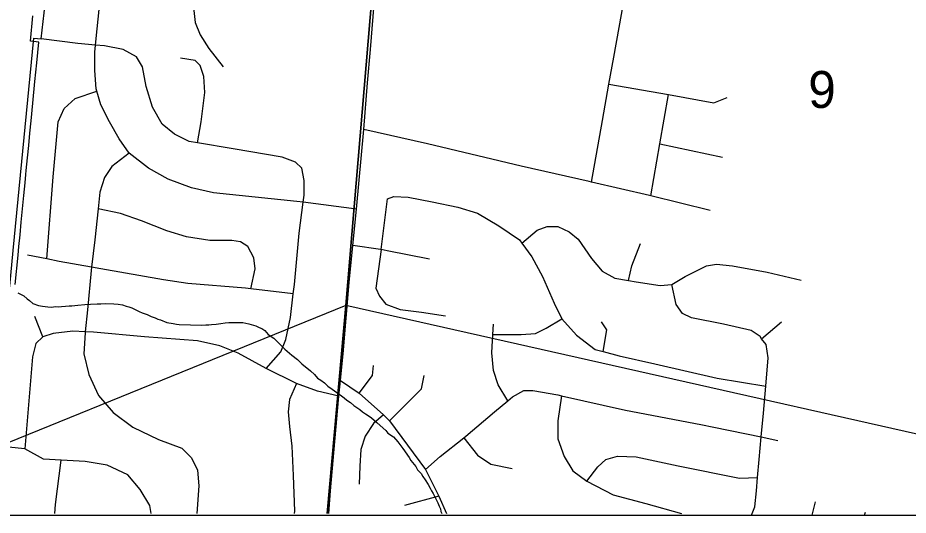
# Model space of a CAD drawing. Extents: x 0 to 34, y 0 to 22.
# Drawn here: x 7.262 to 8.273, y 14 to 14.564 of the extents above; entities that cross this region are included whole.
import ezdxf

# ---------------------------------------------------------------- set-up
doc = ezdxf.new("R2010")
doc.units = 0
for name, color, linetype in [('GM_X_City_Street', 7, 'Continuous'), ('GM_X_Interchange_Ramps', 7, 'Continuous'), ('GM_X_Minor_River', 7, 'Continuous'), ('GM_X_Section', 7, 'Continuous'), ('GM_X_Section_Text', 7, 'Continuous'), ('GM_X_State_Route', 7, 'Continuous'), ('GM_X_State_Shield', 7, 'Continuous'), ('GM_X_Township_Road', 7, 'Continuous'), ('SH_Data', 7, 'Continuous')]:
    doc.layers.add(name, color=color, linetype=linetype)

msp = doc.modelspace()

# ---------------------------------------------------------------- linework, layer by layer
at = {"layer": 'GM_X_City_Street'}
msp.add_lwpolyline([(7.2308, 14.2339), (7.2374, 14.2368), (7.2449, 14.2433), (7.2492, 14.2485), (7.2518, 14.2535), (7.2533, 14.2597), (7.2572, 14.3004), (7.2806, 14.5413), (7.289, 14.5407)], dxfattribs=at)
at = {"layer": 'GM_X_Interchange_Ramps'}
msp.add_lwpolyline([(7.2596, 14.2618), (7.2628, 14.2952), (7.2637, 14.3047), (7.265, 14.3183), (7.2664, 14.3324), (7.2679, 14.3475), (7.2694, 14.3629), (7.2707, 14.3771), (7.2717, 14.3866), (7.2721, 14.3912), (7.2735, 14.4053), (7.2749, 14.4194), (7.2762, 14.4335), (7.2776, 14.4476), (7.2795, 14.4676), (7.2819, 14.4922), (7.284, 14.5132), (7.2863, 14.5368), (7.2768, 14.5377), (7.2796, 14.5666)], dxfattribs=at)
at = {"layer": 'GM_X_Minor_River'}
for points in [[(7.2624, 14.2522), (7.2654, 14.2509), (7.2692, 14.249), (7.2729, 14.2454), (7.2759, 14.2435), (7.2796, 14.2403), (7.286, 14.2379), (7.2906, 14.237), (7.2967, 14.2365), (7.3012, 14.236), (7.305, 14.2367), (7.3084, 14.2366), (7.3119, 14.2369), (7.3164, 14.2371), (7.3206, 14.2374), (7.3237, 14.2377), (7.3305, 14.2383), (7.3385, 14.2389), (7.345, 14.2395), (7.3526, 14.2397), (7.3568, 14.2399), (7.3625, 14.2402), (7.3713, 14.24), (7.3762, 14.2395), (7.3811, 14.2386), (7.3853, 14.2373), (7.3883, 14.2365), (7.3917, 14.2353), (7.4, 14.2313), (7.4037, 14.2297), (7.4094, 14.2276), (7.4139, 14.2256), (7.4184, 14.224), (7.4214, 14.2224), (7.4244, 14.2215), (7.4316, 14.2187), (7.4388, 14.2174)], [(7.4388, 14.2174), (7.4426, 14.2169), (7.4456, 14.2165), (7.4711, 14.2158), (7.4757, 14.2161), (7.4791, 14.216), (7.4821, 14.2163), (7.4875, 14.2166), (7.4928, 14.2176), (7.4978, 14.2182), (7.502, 14.2185), (7.5065, 14.2188), (7.5111, 14.2187), (7.5179, 14.2185), (7.5213, 14.218), (7.5247, 14.2172), (7.5323, 14.2147), (7.5364, 14.2131), (7.5394, 14.2119), (7.5428, 14.2095), (7.5465, 14.2049), (7.5529, 14.2009), (7.561, 14.1931), (7.5655, 14.1884), (7.5733, 14.1814), (7.5796, 14.1767), (7.5848, 14.1716), (7.5945, 14.1637), (7.599, 14.1595), (7.6023, 14.1556), (7.6061, 14.1532), (7.6102, 14.1501), (7.6143, 14.1465), (7.6191, 14.143), (7.6244, 14.1391), (7.6296, 14.1355), (7.6326, 14.1332), (7.6359, 14.1304), (7.6397, 14.1277), (7.6438, 14.1245), (7.6505, 14.1198), (7.6535, 14.1174), (7.6568, 14.1151), (7.6598, 14.1131), (7.6636, 14.1103), (7.6699, 14.1052), (7.6736, 14.1017), (7.68, 14.0962), (7.6822, 14.0931), (7.6885, 14.0888), (7.6937, 14.0834), (7.6992, 14.0756), (7.7066, 14.0656), (7.7084, 14.0621), (7.7139, 14.0551), (7.7158, 14.0516), (7.7202, 14.0473), (7.722, 14.0439), (7.7246, 14.04), (7.7279, 14.035), (7.7304, 14.0307), (7.7319, 14.0277), (7.7337, 14.0246), (7.737, 14.0177), (7.7388, 14.0142), (7.7406, 14.0103), (7.742, 14.0073), (7.7423, 14.0042), (7.7435, 14.0019)]]:
    msp.add_lwpolyline(points, dxfattribs=at)
at = {"layer": 'GM_X_Section'}
msp.add_lwpolyline([(6.6081, 14.0019), (6.679, 14.8357), (7.7155, 15.1965), (7.6347, 14.2379), (7.0538, 14.0019)], dxfattribs=at)
msp.add_lwpolyline([(7.7155, 15.1965), (8.7359, 15.0399), (8.6553, 14.0079), (7.6347, 14.2379)], close=True, dxfattribs=at)
at = {"layer": 'GM_X_State_Route'}
for points in [[(7.6593, 14.4904), (7.6625, 14.5284), (7.6699, 14.6176), (7.6768, 14.6878), (7.6771, 14.6919)], [(7.6154, 14.0019), (7.6173, 14.0275), (7.6244, 14.1094), (7.6268, 14.135), (7.6285, 14.1527), (7.6314, 14.183), (7.6385, 14.2639), (7.6427, 14.3062), (7.6467, 14.3474), (7.6549, 14.4377), (7.6593, 14.4904)]]:
    msp.add_lwpolyline(points, dxfattribs=at)
at = {"layer": 'GM_X_State_Shield'}
for points in [[(7.6133, 14.0019), (7.6347, 14.2379), (7.0538, 14.0019)], [(8.6547, 14.0019), (8.6553, 14.0079), (7.6347, 14.2379), (7.6133, 14.0019)]]:
    msp.add_lwpolyline(points, dxfattribs=at)
at = {"layer": 'GM_X_Township_Road'}
for p, q in [((7.9909, 14.4215), (8.062, 14.4063)), ((7.7294, 14.2905), (7.6815, 14.3001)), ((7.2907, 14.2025), (7.2818, 14.2255)), ((8.1063, 14.2003), (8.1287, 14.2193)), ((7.74, 14.0215), (7.7011, 14.011)), ((8.1637, 14), (8.1673, 14.0151)), ((8.2229, 14), (8.2241, 14.0035))]:
    msp.add_line(p, q, dxfattribs=at)
for points in [[(7.289, 14.5407), (7.3026, 14.6589), (7.306, 14.743)], [(7.4307, 14.739), (7.43, 14.7358), (7.4276, 14.7145), (7.4248, 14.6922), (7.4276, 14.6839), (7.4373, 14.6797), (7.4554, 14.6714), (7.4609, 14.6631), (7.4651, 14.6506), (7.4651, 14.6325), (7.4623, 14.595), (7.4623, 14.5728), (7.4637, 14.5589), (7.4693, 14.545), (7.479, 14.5297), (7.4956, 14.5089)], [(7.9134, 14.378), (7.9256, 14.4478), (7.9331, 14.4891), (7.9387, 14.5196), (7.9508, 14.5873), (7.963, 14.6572)], [(7.6467, 14.3474), (7.5863, 14.3552), (7.579, 14.3561), (7.4845, 14.3658), (7.4595, 14.3714), (7.4331, 14.3811), (7.4109, 14.3936), (7.3887, 14.4109), (7.3776, 14.4269), (7.3665, 14.4464), (7.3568, 14.4658), (7.352, 14.4812), (7.3512, 14.4839), (7.3498, 14.5047), (7.3498, 14.5255), (7.3506, 14.5334), (7.3526, 14.5519), (7.3549, 14.5737), (7.3552, 14.5757)], [(7.5444, 14.1665), (7.5609, 14.1853), (7.5665, 14.1992), (7.572, 14.2242), (7.575, 14.2511), (7.5762, 14.2617), (7.5817, 14.32), (7.5863, 14.3552), (7.5873, 14.3631), (7.5873, 14.3797), (7.5845, 14.3936), (7.5776, 14.4006), (7.5623, 14.4061), (7.5068, 14.4158), (7.4662, 14.4226), (7.4568, 14.4241), (7.4401, 14.4325), (7.4262, 14.4436), (7.4151, 14.463), (7.4081, 14.4866), (7.404, 14.5089), (7.397, 14.52), (7.3818, 14.5283), (7.3609, 14.5325), (7.3506, 14.5334), (7.3304, 14.5353), (7.289, 14.5407)], [(7.4662, 14.4226), (7.4706, 14.4464), (7.4748, 14.4797), (7.4734, 14.4978), (7.4693, 14.5103), (7.4637, 14.5158), (7.447, 14.5186)], [(7.9331, 14.4891), (8.0006, 14.4772), (8.0519, 14.468), (8.0671, 14.4741)], [(7.2955, 14.2907), (7.3026, 14.3839), (7.3081, 14.4464), (7.3151, 14.4616), (7.3276, 14.4727), (7.352, 14.4812)], [(7.9806, 14.3625), (7.9909, 14.4215), (8.0006, 14.4772)], [(7.9105, 14.3787), (7.8336, 14.3962), (7.7274, 14.4215), (7.6549, 14.4377)], [(7.3887, 14.4109), (7.3693, 14.3956), (7.3609, 14.3831), (7.3554, 14.3665), (7.3535, 14.3478), (7.3498, 14.3123), (7.3461, 14.2816), (7.3456, 14.2776), (7.3415, 14.2332), (7.3388, 14.208), (7.3387, 14.2068), (7.3373, 14.1832), (7.3429, 14.1595), (7.354, 14.1359), (7.3706, 14.1165), (7.3929, 14.0998), (7.422, 14.0859), (7.4484, 14.0762), (7.4595, 14.0651), (7.4665, 14.0512), (7.4679, 14.0332), (7.4657, 14.0019)], [(8.0479, 14.3457), (7.9806, 14.3625), (7.9791, 14.3629), (7.9134, 14.378), (7.9105, 14.3787)], [(7.6745, 14.3015), (7.6819, 14.3588), (7.689, 14.3618), (7.7052, 14.3608), (7.7325, 14.3557), (7.7618, 14.3497), (7.784, 14.3426), (7.8083, 14.3285), (7.8315, 14.3123), (7.8343, 14.3085), (7.8457, 14.2931), (7.8578, 14.2708), (7.871, 14.2405), (7.8798, 14.2228), (7.8962, 14.2041), (7.9175, 14.1879), (7.9264, 14.1856), (7.9448, 14.1809), (7.9852, 14.1718), (8.056, 14.1556), (8.111, 14.1465)], [(7.5268, 14.2568), (7.5317, 14.2797), (7.5304, 14.2922), (7.5234, 14.3047), (7.5151, 14.3103), (7.5054, 14.3116), (7.4804, 14.3116), (7.454, 14.3158), (7.4317, 14.3228), (7.4026, 14.3339), (7.379, 14.3422), (7.3535, 14.3478)], [(7.8343, 14.3085), (7.8518, 14.3234), (7.8629, 14.3275), (7.875, 14.3275), (7.8881, 14.3214), (7.8983, 14.3133), (7.9134, 14.2911), (7.9255, 14.2769), (7.9397, 14.2688), (7.9552, 14.2663), (7.964, 14.2648), (7.9913, 14.2607), (8.0045, 14.2618), (8.0196, 14.2709), (8.0438, 14.283), (8.055, 14.285), (8.0732, 14.283), (8.1126, 14.2759), (8.151, 14.2668)], [(7.6815, 14.3001), (7.6745, 14.3015), (7.6738, 14.3016), (7.6427, 14.3062)], [(7.9552, 14.2663), (7.9589, 14.283), (7.969, 14.3083)], [(7.575, 14.2511), (7.5268, 14.2568), (7.5206, 14.2575), (7.4554, 14.263), (7.4276, 14.2672), (7.3568, 14.2797), (7.3461, 14.2816), (7.3095, 14.288), (7.2955, 14.2907), (7.2734, 14.2949)], [(7.6745, 14.3015), (7.6688, 14.2577), (7.6728, 14.2486), (7.6799, 14.2395), (7.6961, 14.2334), (7.7203, 14.2304), (7.7476, 14.2263)], [(8.0947, 14), (8.0984, 14.0095), (8.1004, 14.0277), (8.1017, 14.0427), (8.1035, 14.0631), (8.1059, 14.0888), (8.1085, 14.1157), (8.111, 14.1465), (8.1136, 14.1784), (8.1116, 14.1935), (8.1063, 14.2003), (8.1045, 14.2026), (8.0944, 14.2097), (8.063, 14.2168), (8.0266, 14.2238), (8.0165, 14.2289), (8.0095, 14.239), (8.0045, 14.2618)], [(7.8015, 14.2052), (7.8336, 14.2051), (7.8497, 14.2061), (7.8619, 14.2122), (7.8798, 14.2228)], [(7.8182, 14.1299), (7.8073, 14.148), (7.8022, 14.1642), (7.8002, 14.1844), (7.8015, 14.2052), (7.8022, 14.2167)], [(7.9264, 14.1856), (7.9306, 14.2102), (7.9245, 14.2193)], [(7.6268, 14.135), (7.6026, 14.1408), (7.5785, 14.1493), (7.5444, 14.1665), (7.5123, 14.1839), (7.4915, 14.1922), (7.4665, 14.1978), (7.4063, 14.2024), (7.3484, 14.2075), (7.3388, 14.208), (7.3248, 14.2089), (7.3026, 14.2061), (7.2907, 14.2025), (7.2831, 14.195), (7.279, 14.1797), (7.2706, 14.0754)], [(7.6499, 14.1385), (7.6647, 14.1586), (7.6658, 14.1697)], [(7.6285, 14.1527), (7.6499, 14.1385), (7.6775, 14.114), (7.684, 14.1069), (7.725, 14.0518), (7.74, 14.0215), (7.7486, 14.0019)], [(7.684, 14.1069), (7.7203, 14.1434), (7.7234, 14.1586)], [(7.5785, 14.1493), (7.5706, 14.1311), (7.5692, 14.1172), (7.5706, 14.1006), (7.5734, 14.0783), (7.5748, 14.045), (7.5762, 14.0047), (7.5761, 14.0019)], [(7.725, 14.0518), (7.7416, 14.0666), (7.7684, 14.0879), (7.7709, 14.0898), (7.8032, 14.1172), (7.8182, 14.1299), (7.8235, 14.1343), (7.8366, 14.1414), (7.8467, 14.1414), (7.875, 14.1364), (7.8792, 14.1354), (7.9518, 14.1192), (8.0372, 14.1028)], [(7.8792, 14.1354), (7.875, 14.1071), (7.875, 14.0868), (7.8821, 14.0666), (7.8922, 14.0505), (7.908, 14.0386), (7.9377, 14.0231), (7.9751, 14.0131), (8.0155, 14.0019)], [(7.6775, 14.114), (7.6658, 14.104), (7.6566, 14.0898), (7.6516, 14.0747), (7.6506, 14.0555), (7.6496, 14.0353)], [(8.0372, 14.1028), (8.0519, 14.1), (8.1059, 14.0888), (8.1247, 14.0848)], [(7.7684, 14.0879), (7.784, 14.0681), (7.7992, 14.058), (7.8234, 14.053)], [(7.4138, 14.0019), (7.4123, 14.0109), (7.4012, 14.029), (7.3873, 14.0457), (7.3637, 14.0568), (7.3387, 14.0609), (7.3118, 14.0625), (7.2915, 14.0637), (7.2706, 14.0754), (7.2519, 14.0771)], [(7.3043, 14.0019), (7.3054, 14.0123), (7.3118, 14.0625)], [(7.908, 14.0386), (7.9205, 14.055), (7.9296, 14.0631), (7.9427, 14.0671), (7.964, 14.0661), (8.0115, 14.056), (8.0812, 14.0419), (8.1017, 14.0427)]]:
    msp.add_lwpolyline(points, dxfattribs=at)
at = {"layer": 'SH_Data'}
msp.add_line((2, 14), (9, 14), dxfattribs=at)

# ---------------------------------------------------------------- texts
at = {"layer": 'GM_X_Section_Text'}
msp.add_text('9', height=0.0419, rotation=0, dxfattribs=at).set_placement((8.1592, 14.4621))

doc.saveas('drawing.dxf')
